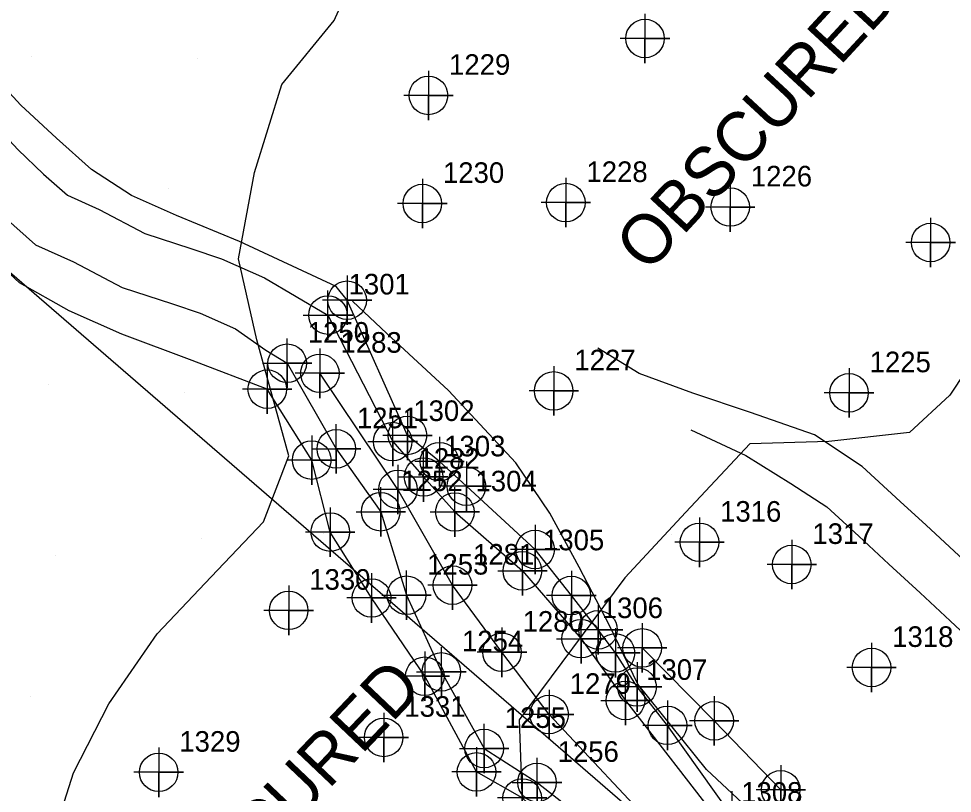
# Model space of a CAD drawing. Extents: x 1497074 to 1501343, y 481943 to 486114.
# Drawn here: x 1498603.4 to 1498716.7, y 485056.3 to 485150.3 of the extents above; entities that cross this region are included whole.
import ezdxf

# ---------------------------------------------------------------- set-up
doc = ezdxf.new("R2010")
doc.units = 0
for name, color, linetype in [('Exist DTM Breakline', 7, 'Continuous'), ('Exist DTM Breakline Cogo Point CELL', 7, 'Continuous'), ('Exist DTM Breakline Underwater', 7, 'Continuous'), ('Exist DTM Breakline Underwater Cogo Number', 7, 'Continuous'), ('Exist DTM Breakline Underwater Cogo Point CELL', 7, 'Continuous'), ('Exist DTM Regular Point CELL', 7, 'Continuous'), ('Exist DTM Regular Point Cogo Number', 7, 'Continuous'), ('Exist Hydro Stream or Body of Water', 7, 'Continuous'), ('Exist Hydro Stream or Body of Water Cogo Number', 7, 'Continuous'), ('Exist Hydro Stream or Body of Water Cogo Point CELL', 7, 'Continuous'), ('PH Exist DTM Boundary', 7, 'Continuous'), ('PH Exist DTM Breakline', 7, 'Continuous'), ('PH Exist DTM Obscure Area', 7, 'Continuous'), ('PH Exist DTM Obscure Area Text', 7, 'Continuous'), ('PH Exist DTM Point', 7, 'Continuous')]:
    doc.layers.add(name, color=color, linetype=linetype)

msp = doc.modelspace()

# ---------------------------------------------------------------- linework, layer by layer
at = {"layer": 'Exist DTM Breakline'}
for points in [[(1498732.74, 485030.21), (1498728.13, 485035.65), (1498720.25, 485042.46), (1498717.11, 485047.82), (1498713.62, 485049.58), (1498705.04, 485051.98), (1498696.55, 485051.35), (1498689.96, 485053.54), (1498682.14, 485064.52), (1498678.45, 485069.18), (1498675.82, 485073.31), (1498673.71, 485076.12), (1498670.47, 485080.28), (1498666.07, 485085.87), (1498657.73, 485093.55), (1498654.46, 485096.53), (1498650.57, 485099.71), (1498643.25, 485116.12)], [(1498722.58, 485017.56), (1498717.39, 485021.69), (1498715.35, 485028.5), (1498705.92, 485036.89), (1498699.02, 485036.8), (1498689.55, 485037.34), (1498680.67, 485042.16), (1498672.01, 485048.68), (1498664.5, 485055.71), (1498658.96, 485058.87), (1498652.68, 485070.48), (1498646.21, 485079.98), (1498641.2, 485087.98), (1498638.95, 485096.72), (1498633.55, 485105.33)], [(1498695.89, 485056.7), (1498687.81, 485065.07), (1498679.07, 485073.92)]]:
    msp.add_lwpolyline(points, dxfattribs=at)
at = {"layer": 'Exist DTM Breakline Cogo Point CELL'}
for points in [[(1498643.25, 485119.12), (1498643.25, 485113.12), (1498643.25, 485116.12), (1498646.25, 485116.12), (1498640.25, 485116.12)], [(1498633.55, 485108.33), (1498633.55, 485102.33), (1498633.55, 485105.33), (1498636.55, 485105.33), (1498630.55, 485105.33)], [(1498650.57, 485102.71), (1498650.57, 485096.71), (1498650.57, 485099.71), (1498653.57, 485099.71), (1498647.57, 485099.71)], [(1498638.95, 485099.72), (1498638.95, 485093.72), (1498638.95, 485096.72), (1498641.95, 485096.72), (1498635.95, 485096.72)], [(1498654.46, 485099.53), (1498654.46, 485093.53), (1498654.46, 485096.53), (1498657.46, 485096.53), (1498651.46, 485096.53)], [(1498657.73, 485096.55), (1498657.73, 485090.55), (1498657.73, 485093.55), (1498660.73, 485093.55), (1498654.73, 485093.55)], [(1498641.2, 485090.98), (1498641.2, 485084.98), (1498641.2, 485087.98), (1498644.2, 485087.98), (1498638.2, 485087.98)], [(1498666.07, 485088.87), (1498666.07, 485082.87), (1498666.07, 485085.87), (1498669.07, 485085.87), (1498663.07, 485085.87)], [(1498646.21, 485082.98), (1498646.21, 485076.98), (1498646.21, 485079.98), (1498649.21, 485079.98), (1498643.21, 485079.98)], [(1498670.47, 485083.28), (1498670.47, 485077.28), (1498670.47, 485080.28), (1498673.47, 485080.28), (1498667.47, 485080.28)], [(1498673.71, 485079.12), (1498673.71, 485073.12), (1498673.71, 485076.12), (1498676.71, 485076.12), (1498670.71, 485076.12)], [(1498675.82, 485076.31), (1498675.82, 485070.31), (1498675.82, 485073.31), (1498678.82, 485073.31), (1498672.82, 485073.31)], [(1498679.07, 485076.92), (1498679.07, 485070.92), (1498679.07, 485073.92), (1498682.07, 485073.92), (1498676.07, 485073.92)], [(1498652.68, 485073.48), (1498652.68, 485067.48), (1498652.68, 485070.48), (1498655.68, 485070.48), (1498649.68, 485070.48)], [(1498678.45, 485072.18), (1498678.45, 485066.18), (1498678.45, 485069.18), (1498681.45, 485069.18), (1498675.45, 485069.18)], [(1498687.81, 485068.07), (1498687.81, 485062.07), (1498687.81, 485065.07), (1498690.81, 485065.07), (1498684.81, 485065.07)], [(1498682.14, 485067.52), (1498682.14, 485061.52), (1498682.14, 485064.52), (1498685.14, 485064.52), (1498679.14, 485064.52)], [(1498658.96, 485061.87), (1498658.96, 485055.87), (1498658.96, 485058.87), (1498661.96, 485058.87), (1498655.96, 485058.87)], [(1498695.89, 485059.7), (1498695.89, 485053.7), (1498695.89, 485056.7), (1498698.89, 485056.7), (1498692.89, 485056.7)], [(1498664.5, 485058.71), (1498664.5, 485052.71), (1498664.5, 485055.71), (1498667.5, 485055.71), (1498661.5, 485055.71)], [(1498689.96, 485056.54), (1498689.96, 485050.54), (1498689.96, 485053.54), (1498692.96, 485053.54), (1498686.96, 485053.54)]]:
    msp.add_lwpolyline(points, dxfattribs=at)
for centre in [(1498643.25, 485116.12), (1498633.55, 485105.33), (1498650.57, 485099.71), (1498638.95, 485096.72), (1498654.46, 485096.53), (1498657.73, 485093.55), (1498641.2, 485087.98), (1498666.07, 485085.87), (1498646.21, 485079.98), (1498670.47, 485080.28), (1498673.71, 485076.12), (1498679.07, 485073.92), (1498675.82, 485073.31), (1498652.68, 485070.48), (1498678.45, 485069.18), (1498682.14, 485064.52), (1498687.81, 485065.07), (1498658.96, 485058.87), (1498695.89, 485056.7), (1498664.5, 485055.71)]:
    msp.add_circle(centre, 2.34, dxfattribs=at)
at = {"layer": 'Exist DTM Breakline Underwater'}
msp.add_lwpolyline([(1498716.29, 485037.62), (1498716.12, 485040.27), (1498710.06, 485044.33), (1498692.08, 485045.67), (1498681.65, 485051.03), (1498667.77, 485065.84), (1498662.05, 485073.39), (1498656.04, 485081.53), (1498649.42, 485093.16), (1498639.94, 485107.25)], dxfattribs=at)
at = {"layer": 'Exist DTM Breakline Underwater Cogo Point CELL'}
for points in [[(1498639.94, 485110.25), (1498639.94, 485104.25), (1498639.94, 485107.25), (1498642.94, 485107.25), (1498636.94, 485107.25)], [(1498649.42, 485096.16), (1498649.42, 485090.16), (1498649.42, 485093.16), (1498652.42, 485093.16), (1498646.42, 485093.16)], [(1498656.04, 485084.53), (1498656.04, 485078.53), (1498656.04, 485081.53), (1498659.04, 485081.53), (1498653.04, 485081.53)], [(1498662.05, 485076.39), (1498662.05, 485070.39), (1498662.05, 485073.39), (1498665.05, 485073.39), (1498659.05, 485073.39)], [(1498667.77, 485068.84), (1498667.77, 485062.84), (1498667.77, 485065.84), (1498670.77, 485065.84), (1498664.77, 485065.84)]]:
    msp.add_lwpolyline(points, dxfattribs=at)
for centre in [(1498639.94, 485107.25), (1498649.42, 485093.16), (1498656.04, 485081.53), (1498662.05, 485073.39), (1498667.77, 485065.84)]:
    msp.add_circle(centre, 2.34, dxfattribs=at)
at = {"layer": 'Exist DTM Regular Point CELL'}
for points in [[(1498679.41, 485150.89), (1498679.41, 485144.89), (1498679.41, 485147.89), (1498682.41, 485147.89), (1498676.41, 485147.89)], [(1498653.12, 485143.98), (1498653.12, 485137.98), (1498653.12, 485140.98), (1498656.12, 485140.98), (1498650.12, 485140.98)], [(1498652.38, 485130.86), (1498652.38, 485124.86), (1498652.38, 485127.86), (1498655.38, 485127.86), (1498649.38, 485127.86)], [(1498669.8, 485130.97), (1498669.8, 485124.97), (1498669.8, 485127.97), (1498672.8, 485127.97), (1498666.8, 485127.97)], [(1498689.76, 485130.43), (1498689.76, 485124.43), (1498689.76, 485127.43), (1498692.76, 485127.43), (1498686.76, 485127.43)], [(1498714.09, 485126.13), (1498714.09, 485120.13), (1498714.09, 485123.13), (1498717.09, 485123.13), (1498711.09, 485123.13)], [(1498668.33, 485108.11), (1498668.33, 485102.11), (1498668.33, 485105.11), (1498671.33, 485105.11), (1498665.33, 485105.11)], [(1498704.18, 485107.88), (1498704.18, 485101.88), (1498704.18, 485104.88), (1498707.18, 485104.88), (1498701.18, 485104.88)], [(1498686.03, 485089.74), (1498686.03, 485083.74), (1498686.03, 485086.74), (1498689.03, 485086.74), (1498683.03, 485086.74)], [(1498697.23, 485087.04), (1498697.23, 485081.04), (1498697.23, 485084.04), (1498700.23, 485084.04), (1498694.23, 485084.04)], [(1498636.15, 485081.48), (1498636.15, 485075.48), (1498636.15, 485078.48), (1498639.15, 485078.48), (1498633.15, 485078.48)], [(1498706.92, 485074.54), (1498706.92, 485068.54), (1498706.92, 485071.54), (1498709.92, 485071.54), (1498703.92, 485071.54)], [(1498647.69, 485066.06), (1498647.69, 485060.06), (1498647.69, 485063.06), (1498650.69, 485063.06), (1498644.69, 485063.06)], [(1498620.37, 485061.82), (1498620.37, 485055.82), (1498620.37, 485058.82), (1498623.37, 485058.82), (1498617.37, 485058.82)]]:
    msp.add_lwpolyline(points, dxfattribs=at)
for centre in [(1498679.41, 485147.89), (1498653.12, 485140.98), (1498669.8, 485127.97), (1498652.38, 485127.86), (1498689.76, 485127.43), (1498714.09, 485123.13), (1498668.33, 485105.11), (1498704.18, 485104.88), (1498686.03, 485086.74), (1498697.23, 485084.04), (1498636.15, 485078.48), (1498706.92, 485071.54), (1498647.69, 485063.06), (1498620.37, 485058.82)]:
    msp.add_circle(centre, 2.34, dxfattribs=at)
at = {"layer": 'Exist Hydro Stream or Body of Water'}
for points in [[(1498640.92, 485114.32), (1498648.78, 485098.96), (1498652.53, 485094.67), (1498656.33, 485090.42), (1498664.53, 485083.27), (1498671.66, 485075.04), (1498677.05, 485067.54), (1498688.59, 485052.63), (1498697.34, 485049.69), (1498712.82, 485047.72), (1498719.79, 485040.49), (1498726.29, 485034.17), (1498730.33, 485028.02)], [(1498635.97, 485108.47), (1498641.93, 485098.08), (1498647.33, 485090.45), (1498650.46, 485080.31), (1498654.69, 485071.01), (1498659.88, 485061.71), (1498666.3, 485057.59), (1498674.73, 485050.99), (1498685.19, 485045.13), (1498692.03, 485040.34), (1498698.43, 485038.57), (1498704.27, 485041.72), (1498707.73, 485040.64), (1498712.52, 485035.85), (1498714.44, 485033.92)]]:
    msp.add_lwpolyline(points, dxfattribs=at)
at = {"layer": 'Exist Hydro Stream or Body of Water Cogo Point CELL'}
for points in [[(1498637.92, 485114.32), (1498643.92, 485114.32), (1498640.92, 485114.32), (1498640.92, 485111.32), (1498640.92, 485117.32)], [(1498632.97, 485108.47), (1498638.97, 485108.47), (1498635.97, 485108.47), (1498635.97, 485105.47), (1498635.97, 485111.47)], [(1498645.78, 485098.96), (1498651.78, 485098.96), (1498648.78, 485098.96), (1498648.78, 485095.96), (1498648.78, 485101.96)], [(1498638.93, 485098.08), (1498644.93, 485098.08), (1498641.93, 485098.08), (1498641.93, 485095.08), (1498641.93, 485101.08)], [(1498649.53, 485094.67), (1498655.53, 485094.67), (1498652.53, 485094.67), (1498652.53, 485091.67), (1498652.53, 485097.67)], [(1498644.33, 485090.45), (1498650.33, 485090.45), (1498647.33, 485090.45), (1498647.33, 485087.45), (1498647.33, 485093.45)], [(1498653.33, 485090.42), (1498659.33, 485090.42), (1498656.33, 485090.42), (1498656.33, 485087.42), (1498656.33, 485093.42)], [(1498661.53, 485083.27), (1498667.53, 485083.27), (1498664.53, 485083.27), (1498664.53, 485080.27), (1498664.53, 485086.27)], [(1498647.46, 485080.31), (1498653.46, 485080.31), (1498650.46, 485080.31), (1498650.46, 485077.31), (1498650.46, 485083.31)], [(1498668.66, 485075.04), (1498674.66, 485075.04), (1498671.66, 485075.04), (1498671.66, 485072.04), (1498671.66, 485078.04)], [(1498651.69, 485071.01), (1498657.69, 485071.01), (1498654.69, 485071.01), (1498654.69, 485068.01), (1498654.69, 485074.01)], [(1498674.05, 485067.54), (1498680.05, 485067.54), (1498677.05, 485067.54), (1498677.05, 485064.54), (1498677.05, 485070.54)], [(1498656.88, 485061.71), (1498662.88, 485061.71), (1498659.88, 485061.71), (1498659.88, 485058.71), (1498659.88, 485064.71)], [(1498663.3, 485057.59), (1498669.3, 485057.59), (1498666.3, 485057.59), (1498666.3, 485054.59), (1498666.3, 485060.59)]]:
    msp.add_lwpolyline(points, dxfattribs=at)
for centre in [(1498640.92, 485114.32), (1498635.97, 485108.47), (1498648.78, 485098.96), (1498641.93, 485098.08), (1498652.53, 485094.67), (1498647.33, 485090.45), (1498656.33, 485090.42), (1498664.53, 485083.27), (1498650.46, 485080.31), (1498671.66, 485075.04), (1498654.69, 485071.01), (1498677.05, 485067.54), (1498659.88, 485061.71), (1498666.3, 485057.59)]:
    msp.add_circle(centre, 2.34, dxfattribs=at)
at = {"layer": 'PH Exist DTM Boundary'}
for points in [[(1498924.23, 484841.06), (1498545.19, 485168.9), (1498846.5, 485569.16), (1499227.59, 485244.03)], [(1498186.43, 484771.69), (1498560.82, 484438.23), (1498782.89, 484653.31), (1498924.23, 484841.06), (1498545.19, 485168.9), (1498406.94, 484985.26)]]:
    msp.add_lwpolyline(points, close=True, dxfattribs=at)
at = {"layer": 'PH Exist DTM Breakline'}
for points in [[(1498643.25, 485116.12), (1498641.93, 485117.79), (1498630.19, 485123.26), (1498622.53, 485126.39), (1498617.07, 485128.84), (1498612.21, 485132), (1498607.96, 485135.81), (1498603.64, 485139.8), (1498598.46, 485145.39), (1498595.36, 485150.58), (1498592.75, 485155.81), (1498589.6, 485160.41), (1498585.1, 485164.63), (1498579.59, 485167.7), (1498575.08, 485170.11), (1498567.59, 485170.68), (1498562.35, 485172.69), (1498558.05, 485176.43), (1498549.24, 485182.41)], [(1498633.55, 485105.33), (1498624.45, 485108.81), (1498615.9, 485111.99), (1498609.49, 485114.84), (1498603.49, 485118.25), (1498598, 485123.27), (1498592.61, 485128.38), (1498588.98, 485134.07), (1498585.03, 485141.17), (1498582.59, 485146.51), (1498577.71, 485152.66), (1498572.01, 485156.75), (1498564.68, 485158.21), (1498558.97, 485159.65), (1498553.4, 485162.27), (1498546.6, 485165.4), (1498541.41, 485168.23), (1498535.25, 485173.22)], [(1498581.62, 485154.02), (1498584.84, 485148.74), (1498589.34, 485141.25), (1498595.08, 485132.75), (1498598.25, 485129.4), (1498601.63, 485126.19), (1498605.43, 485122.85), (1498610.04, 485120.77), (1498615.92, 485117.66), (1498622.04, 485115.68), (1498625.42, 485114.54), (1498629.71, 485112.64), (1498633.38, 485110.05), (1498635.97, 485108.47)], [(1498590.89, 485152.4), (1498595.31, 485145.06), (1498600.62, 485137.19), (1498603.25, 485134.4), (1498606.4, 485131.41), (1498609.31, 485128.87), (1498613.16, 485127.13), (1498618.69, 485124.2), (1498624.26, 485122.39), (1498627.98, 485121.14), (1498633.21, 485118.83), (1498640.92, 485114.32)], [(1498722.24, 485041.06), (1498719.18, 485045.8), (1498716.49, 485049.58), (1498712.95, 485052.85), (1498707.97, 485054.75), (1498701.72, 485053.95), (1498696.12, 485053.38), (1498691.23, 485055.06), (1498686.87, 485059.15), (1498678.55, 485069.54), (1498675.08, 485076.74), (1498671.43, 485083.74), (1498667.87, 485090.27), (1498663.71, 485096.4), (1498655.56, 485105.17), (1498648.08, 485112.1), (1498643.88, 485115.99)], [(1498726.51, 485076.8), (1498722.03, 485080.94), (1498716.93, 485085.66), (1498713.53, 485088.8), (1498710.39, 485091.7), (1498705.79, 485095.95), (1498700.01, 485099.8), (1498692.22, 485102.48), (1498685.22, 485104.84), (1498678.72, 485107.21), (1498673.67, 485110.3)], [(1498684.99, 485100.38), (1498691.67, 485097.26), (1498697.1, 485093.89), (1498701.49, 485091.03), (1498705.36, 485087.47), (1498709.02, 485084.1), (1498712.8, 485080.61), (1498716.48, 485077.2), (1498719.56, 485074.31)]]:
    msp.add_lwpolyline(points, dxfattribs=at)
at = {"layer": 'PH Exist DTM Obscure Area'}
for points in [[(1498636.16, 485097.24), (1498632.27, 485111.32), (1498630.06, 485121.15), (1498631.99, 485131.64), (1498635.31, 485142.31), (1498641.67, 485150.09), (1498645.13, 485157.75)], [(1498786.56, 485142.57), (1498778.79, 485133.61), (1498764.69, 485124.32), (1498755.26, 485123.73), (1498746.22, 485125.77), (1498732.42, 485122.81), (1498722.14, 485113.21), (1498716.44, 485104.59), (1498711.53, 485100.07), (1498701.72, 485098.98), (1498692.14, 485098.71), (1498684.36, 485090.41), (1498676.97, 485082.41), (1498664.13, 485065.2)], [(1498664.13, 485065.2), (1498664.63, 485051.67), (1498665.76, 485044.19), (1498661.43, 485038.57), (1498654.58, 485032.74), (1498646.02, 485028.08), (1498638.13, 485022.6), (1498629.97, 485019.07), (1498621.76, 485016.91), (1498614.88, 485019.04), (1498608.07, 485025.52), (1498604.99, 485035.11), (1498606.09, 485046.43), (1498610.01, 485058.77), (1498614.32, 485067.12), (1498620.17, 485075.63), (1498626.73, 485082.53), (1498633.1, 485089.24), (1498636.16, 485097.24)]]:
    msp.add_lwpolyline(points, dxfattribs=at)
at = {"layer": 'PH Exist DTM Point'}
for p, q in [((1498604.98, 485145.74), (1498604.98, 485145.74)), ((1498625.04, 485145.47), (1498625.04, 485145.47)), ((1498621.56, 485129.64), (1498621.56, 485129.64)), ((1498607.05, 485105.84), (1498607.05, 485105.84)), ((1498623.51, 485104.94), (1498623.51, 485104.94)), ((1498625.61, 485087.25), (1498625.61, 485087.25)), ((1498640.43, 485087.82), (1498640.43, 485087.82)), ((1498682.57, 485087.74), (1498682.57, 485087.74)), ((1498607.81, 485085.16), (1498607.81, 485085.16)), ((1498604.75, 485068.07), (1498604.75, 485068.07))]:
    msp.add_line(p, q, dxfattribs=at)

# ---------------------------------------------------------------- texts
at = {"layer": 'Exist DTM Breakline Underwater Cogo Number'}
for s, p in [('1283', (1498642.44, 485109.75)), ('1282', (1498651.92, 485095.66)), ('1281', (1498658.54, 485084.03)), ('1280', (1498664.55, 485075.89)), ('1279', (1498670.27, 485068.34))]:
    msp.add_text(s, height=2.5, dxfattribs=at).set_placement(p)
at = {"layer": 'Exist DTM Regular Point Cogo Number'}
for s, p in [('1229', (1498655.62, 485143.48)), ('1230', (1498654.88, 485130.36)), ('1228', (1498672.3, 485130.47)), ('1226', (1498692.26, 485129.93)), ('1227', (1498670.83, 485107.61)), ('1225', (1498706.68, 485107.38)), ('1316', (1498688.53, 485089.24)), ('1317', (1498699.73, 485086.54)), ('1330', (1498638.65, 485080.98)), ('1318', (1498709.42, 485074.04)), ('1331', (1498650.19, 485065.56)), ('1329', (1498622.87, 485061.32))]:
    msp.add_text(s, height=2.5, dxfattribs=at).set_placement(p)
at = {"layer": 'Exist Hydro Stream or Body of Water Cogo Number'}
for s, p in [('1301', (1498643.42, 485116.82)), ('1250', (1498638.47, 485110.97)), ('1251', (1498644.43, 485100.58)), ('1302', (1498651.28, 485101.46)), ('1303', (1498655.03, 485097.17)), ('1252', (1498649.83, 485092.95)), ('1304', (1498658.83, 485092.92)), ('1305', (1498667.03, 485085.77)), ('1253', (1498652.96, 485082.82)), ('1306', (1498674.16, 485077.54)), ('1254', (1498657.19, 485073.51)), ('1307', (1498679.55, 485070.04)), ('1255', (1498662.38, 485064.21)), ('1256', (1498668.8, 485060.09)), ('1308', (1498691.09, 485055.13))]:
    msp.add_text(s, height=2.5, dxfattribs=at).set_placement(p)
at = {"layer": 'PH Exist DTM Obscure Area Text'}
for rotation, p in [(47.2398, (1498679.76, 485119.29)), (46.4845, (1498621.35, 485035.99))]:
    msp.add_text('OBSCURED', height=6, rotation=rotation, dxfattribs=at).set_placement(p)

doc.saveas('drawing.dxf')
